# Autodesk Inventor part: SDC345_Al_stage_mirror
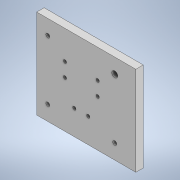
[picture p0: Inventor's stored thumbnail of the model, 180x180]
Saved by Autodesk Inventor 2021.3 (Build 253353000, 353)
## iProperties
Created: 2022-02
Part Number: SDC345_Al_stage_mirror
Material: 一般
Document SubType Name: Modeling
Designer: kengo
Density: 1 g/cm^3
Appearance: 既定
Author: kengo
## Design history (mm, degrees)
derived "SDC3_Alstage.ipt"
feature "ソリッド1::SDC3_Alstage.ipt" dims "d0" = 10
tag "TaggingFeature1"
node "ソリッド1"
